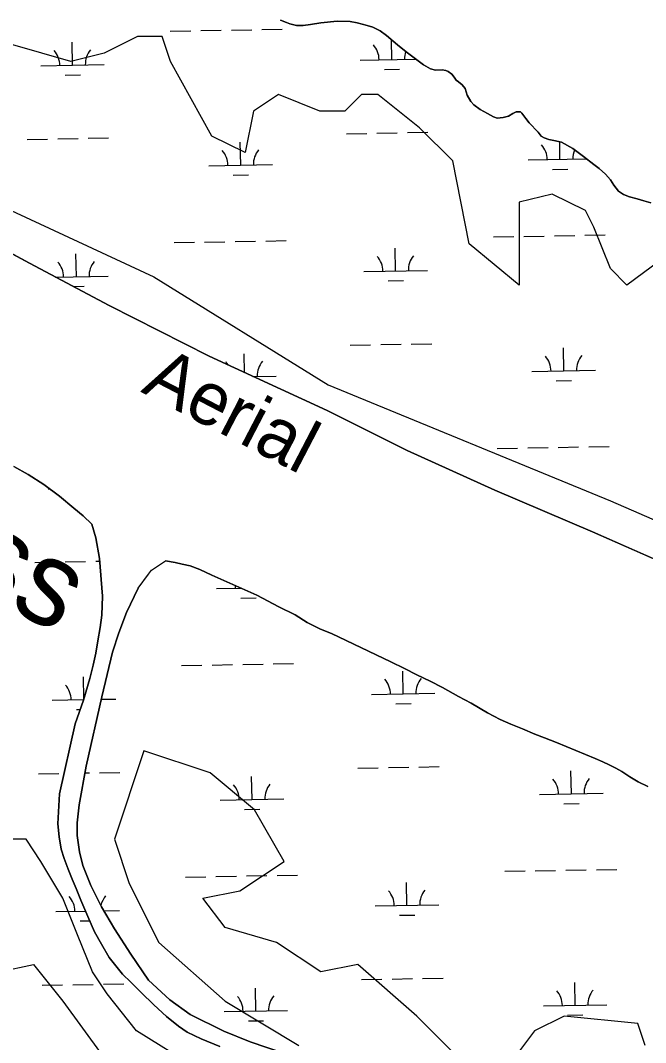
# Model space of a CAD drawing. Extents: x 3914892 to 3953151, y 242587 to 268572.
# Drawn here: x 3945998 to 3946980, y 254674 to 256282 of the extents above; entities that cross this region are included whole.
import ezdxf

# ---------------------------------------------------------------- set-up
doc = ezdxf.new("R2010")
doc.units = 0
for name, color, linetype in [('V-RIVR-IDEN', 7, 'Continuous'), ('V-SITE-VEGE', 7, 'Continuous'), ('V-TOPO-SHOR', 7, 'Continuous'), ('V-WETL-SWMP', 7, 'Continuous')]:
    doc.layers.add(name, color=color, linetype=linetype)

msp = doc.modelspace()

# ---------------------------------------------------------------- linework, layer by layer
at = {"layer": 'V-SITE-VEGE'}
for points in [[(3947003.4, 255904.8), (3946951.2, 255865.7), (3946925.1, 255891.8), (3946899, 255957), (3946886, 255983.1), (3946833.8, 256009.1), (3946781.6, 255996.1), (3946781.6, 255917.8), (3946781.6, 255865.7), (3946703.4, 255930.9), (3946677.3, 256061.3), (3946625.1, 256113.5), (3946559.9, 256165.7), (3946533.8, 256165.7), (3946507.7, 256139.6), (3946468.6, 256139.6), (3946403.4, 256165.7), (3946364.3, 256139.6), (3946351.2, 256074.4), (3946299, 256100.4), (3946233.8, 256217.8), (3946220.8, 256257), (3946181.7, 256257), (3946129.5, 256230.9), (3946077.3, 256217.8), (3945986, 256243.9)], [(3945646.9, 256139.6), (3946207.7, 255878.7), (3946481.6, 255709.1), (3946925.1, 255526.5), (3947225.1, 255396.1)], [(3946678.6, 254658.3), (3946620.7, 254716.2), (3946528, 254797.3), (3946470.1, 254785.8), (3946400.6, 254832.1), (3946319.5, 254855.3), (3946284.7, 254901.6), (3946342.7, 254913.2), (3946412.2, 254959.5), (3946365.8, 255040.6), (3946296.3, 255098.6), (3946192.1, 255133.3), (3946145.7, 254994.3), (3946168.9, 254924.8), (3946215.2, 254832.1), (3946319.5, 254739.4), (3946435.4, 254669.9)], [(3946273.2, 254635.1), (3946180.5, 254693.1), (3946134.1, 254751), (3946111, 254785.8), (3946087.8, 254843.7), (3946064.6, 254901.6), (3946029.9, 254959.5), (3946006.7, 254994.3), (3945960.4, 254994.3)], [(3945856.1, 254762.6), (3946018.3, 254797.3), (3946064.6, 254739.4), (3946157.3, 254612)], [(3946979.9, 254669.9), (3946968.3, 254704.7), (3946852.4, 254716.2), (3946806.1, 254693.1), (3946771.3, 254646.7)]]:
    msp.add_lwpolyline(points, dxfattribs=at)
at = {"layer": 'V-TOPO-SHOR'}
for points in [[(3946792.3, 256128.1), (3946786.1, 256136.6), (3946783.7, 256138.2), (3946781.1, 256138.3), (3946777.1, 256138.5), (3946772.1, 256136), (3946764.9, 256131.7), (3946756.5, 256129.3), (3946747.1, 256128.6), (3946741.3, 256130.7), (3946732.1, 256135.6), (3946720.4, 256142.2), (3946710.6, 256149.5), (3946705.8, 256154.7), (3946700.2, 256164.8), (3946696.8, 256175), (3946692.3, 256180.8), (3946686.4, 256185.7), (3946682.6, 256188.5), (3946679.5, 256193.2), (3946676, 256197.8), (3946670.3, 256202.1), (3946666.5, 256203.7), (3946660.6, 256204.4), (3946650.2, 256204), (3946642.5, 256205.9), (3946631.4, 256212.4), (3946618.8, 256221.8), (3946604.2, 256232.7), (3946590.4, 256243.9), (3946573.3, 256258.7), (3946563.1, 256266), (3946552, 256271.6), (3946542.9, 256274.5), (3946527, 256278.5), (3946516.3, 256280.3), (3946496, 256281.2), (3946470, 256278.6), (3946453.7, 256275.6), (3946442.5, 256274), (3946431.9, 256274.4), (3946421.6, 256276.7), (3946415.9, 256279), (3946406.9, 256282.7)], [(3946988.7, 255995.3), (3946977.8, 255998.7), (3946967.3, 256001.4), (3946955, 256004.6), (3946945.7, 256008.5), (3946938, 256013.8), (3946930.8, 256023.1), (3946925.1, 256031.7), (3946917.3, 256040.4), (3946907.3, 256049.3), (3946899.4, 256055.8), (3946882.7, 256068.4), (3946866.1, 256080.8), (3946848.1, 256090.7), (3946836.4, 256093.2), (3946828.3, 256094.9), (3946820.9, 256097.4), (3946816.6, 256100.1), (3946811.5, 256106.3), (3946797.6, 256120.9), (3946792.3, 256128.1)], [(3945916.1, 255951.8), (3946012, 255900.5), (3946137.4, 255833.6), (3946294.5, 255753.9), (3946480.1, 255668.6), (3946605.9, 255605.7), (3946743.7, 255543.1), (3946897.2, 255477.8), (3947054, 255408.5)], [(3946110.1, 255490.1), (3946096.6, 255502.9), (3946081.7, 255515), (3946059.2, 255534.1), (3946034.9, 255552.2), (3946009.9, 255567.8), (3945987.5, 255580.4)], [(3946127, 255376.4), (3946122, 255436.1), (3946116.7, 255468.6), (3946110.1, 255490.1)], [(3946183.1, 255389.4), (3946199, 255411.2), (3946203.7, 255417.5), (3946225.9, 255432.3)], [(3946369.7, 255378.4), (3946298.8, 255409.7), (3946279.8, 255418.4), (3946264.7, 255424.3), (3946252.3, 255426.9), (3946241, 255429.4), (3946225.9, 255432.3)], [(3946183.1, 255389.4), (3946164.8, 255351.1), (3946152.4, 255319.2), (3946142.9, 255288.4), (3946125.9, 255218.2), (3946101, 255109.4), (3946090.5, 255048.4), (3946086.9, 255019.9), (3946087.2, 255000.1), (3946090.7, 254974.5), (3946096, 254953), (3946108.8, 254921.3), (3946125.3, 254888.2), (3946145.6, 254853.1), (3946171.2, 254813.3), (3946199.4, 254772.7), (3946232.7, 254741.7), (3946264.9, 254718.6), (3946317.7, 254692.4), (3946358.9, 254675.8), (3946413.2, 254657.3)], [(3946311.4, 254668.3), (3946282, 254680.5), (3946260.2, 254690.8), (3946246.2, 254700.5), (3946227.3, 254715.6), (3946207.8, 254733.7), (3946187.8, 254753.1), (3946171.5, 254769.2), (3946158.6, 254782.3), (3946137.4, 254808.3), (3946125.1, 254829.4), (3946114.6, 254848.7), (3946103.7, 254873), (3946092.8, 254898.3), (3946085.5, 254916.6), (3946079.3, 254931.6), (3946072.9, 254947.3), (3946066.8, 254964), (3946061.9, 254978.6), (3946058.7, 254997.8), (3946056.7, 255018.7), (3946059.6, 255065.5), (3946083.9, 255176), (3946097, 255213), (3946107.1, 255246.9), (3946112.2, 255267.9), (3946116.7, 255287), (3946119.5, 255306.1), (3946123.1, 255327.1), (3946125.9, 255346.8), (3946127, 255376.4)], [(3946983.8, 255077.3), (3946969, 255084.5), (3946955.7, 255092.2), (3946943.1, 255100.9), (3946933.7, 255106), (3946923.5, 255111.5), (3946913.2, 255116.2), (3946901.4, 255121.4), (3946840.6, 255146.3), (3946821.5, 255153.8), (3946806.2, 255159.6), (3946787.2, 255167.7), (3946768.5, 255175.4), (3946752.1, 255182.4), (3946732, 255193.2), (3946706.2, 255208.5), (3946686.5, 255218.9), (3946661.3, 255233.1), (3946642, 255243.1), (3946620.9, 255253), (3946601.6, 255262.9), (3946580, 255273.2), (3946486.8, 255318), (3946469.7, 255324.8), (3946448.6, 255335.2), (3946429.8, 255347.3), (3946404.2, 255359.7), (3946369.7, 255378.4)]]:
    msp.add_lwpolyline(points, dxfattribs=at)
at = {"layer": 'V-WETL-SWMP'}
for p, q in [((3946406.9, 256282.7), (3946415.9, 256279)), ((3946415.9, 256279), (3946421.6, 256276.7)), ((3946421.6, 256276.7), (3946431.9, 256274.4)), ((3946431.9, 256274.4), (3946442.5, 256274)), ((3946442.5, 256274), (3946453.7, 256275.6)), ((3946453.7, 256275.6), (3946470, 256278.6)), ((3946470, 256278.6), (3946496, 256281.2)), ((3946496, 256281.2), (3946516.3, 256280.3)), ((3946516.3, 256280.3), (3946527, 256278.5)), ((3946527, 256278.5), (3946542.9, 256274.5)), ((3946542.9, 256274.5), (3946552, 256271.6)), ((3946233.5, 256265.3), (3946265.5, 256265.9)), ((3946281.5, 256266.2), (3946313.5, 256266.7)), ((3946329.5, 256267), (3946361.5, 256267.6)), ((3946377.5, 256267.9), (3946409.5, 256268.4)), ((3946552, 256271.6), (3946563.1, 256266)), ((3946563.1, 256266), (3946573.3, 256258.7)), ((3946573.3, 256258.7), (3946590.4, 256243.9)), ((3946079.8, 256211.8), (3946079.2, 256247.8)), ((3946581.7, 256220.8), (3946581.1, 256251.9)), ((3946590.4, 256243.9), (3946604.2, 256232.7)), ((3946604.2, 256232.7), (3946618.8, 256221.8)), ((3946029.8, 256210.9), (3946129.8, 256212.7)), ((3946531.7, 256219.9), (3946619.3, 256221.4)), ((3946618.8, 256221.8), (3946631.4, 256212.4)), ((3946631.4, 256212.4), (3946642.5, 256205.9)), ((3946068.1, 256196.2), (3946092.1, 256196.6)), ((3946569.9, 256205.1), (3946593.9, 256205.6)), ((3946642.5, 256205.9), (3946650.2, 256204)), ((3946650.2, 256204), (3946660.6, 256204.4)), ((3946660.6, 256204.4), (3946666.5, 256203.7)), ((3946666.5, 256203.7), (3946670.3, 256202.1)), ((3946670.3, 256202.1), (3946676, 256197.8)), ((3946676, 256197.8), (3946679.5, 256193.2)), ((3946679.5, 256193.2), (3946682.6, 256188.5)), ((3946682.6, 256188.5), (3946686.4, 256185.7)), ((3946686.4, 256185.7), (3946692.3, 256180.8)), ((3946692.3, 256180.8), (3946696.8, 256175)), ((3946696.8, 256175), (3946700.2, 256164.8)), ((3946700.2, 256164.8), (3946705.8, 256154.7)), ((3946705.8, 256154.7), (3946710.6, 256149.5)), ((3946710.6, 256149.5), (3946720.4, 256142.2)), ((3946720.4, 256142.2), (3946732.1, 256135.6)), ((3946732.1, 256135.6), (3946741.3, 256130.7)), ((3946741.3, 256130.7), (3946747.1, 256128.6)), ((3946747.1, 256128.6), (3946756.5, 256129.3)), ((3946756.5, 256129.3), (3946764.9, 256131.7)), ((3946764.9, 256131.7), (3946772.1, 256136)), ((3946772.1, 256136), (3946777.1, 256138.5)), ((3946777.1, 256138.5), (3946781.1, 256138.3)), ((3946781.1, 256138.3), (3946783.7, 256138.2)), ((3946783.7, 256138.2), (3946786.1, 256136.6)), ((3946786.1, 256136.6), (3946792.3, 256128.1)), ((3946792.3, 256128.1), (3946797.6, 256120.9)), ((3946797.6, 256120.9), (3946811.5, 256106.3)), ((3946008.5, 256095.1), (3946040.5, 256095.6)), ((3946056.5, 256095.9), (3946088.5, 256096.5)), ((3946104.5, 256096.8), (3946136.5, 256097.4)), ((3946510.3, 256104), (3946542.3, 256104.6)), ((3946558.3, 256104.9), (3946590.3, 256105.5)), ((3946606.3, 256105.8), (3946638.3, 256106.3)), ((3946811.5, 256106.3), (3946816.6, 256100.1)), ((3946816.6, 256100.1), (3946820.9, 256097.4)), ((3946820.9, 256097.4), (3946828.3, 256094.9)), ((3946344.1, 256054.6), (3946343.5, 256090.6)), ((3946828.3, 256094.9), (3946836.4, 256093.2)), ((3946836.4, 256093.2), (3946848.1, 256090.7)), ((3946845.9, 256063.6), (3946845.5, 256091.3)), ((3946848.1, 256090.7), (3946866.1, 256080.8)), ((3946866.1, 256080.8), (3946882.7, 256068.4)), ((3946796, 256062.7), (3946888, 256064.4)), ((3946882.7, 256068.4), (3946899.4, 256055.8)), ((3946294.1, 256053.7), (3946394.1, 256055.5)), ((3946834.2, 256048), (3946858.2, 256048.4)), ((3946899.4, 256055.8), (3946907.3, 256049.3)), ((3946907.3, 256049.3), (3946917.3, 256040.4)), ((3946332.4, 256039), (3946356.4, 256039.4)), ((3946917.3, 256040.4), (3946925.1, 256031.7)), ((3946925.1, 256031.7), (3946930.8, 256023.1)), ((3946930.8, 256023.1), (3946938, 256013.8)), ((3946938, 256013.8), (3946945.7, 256008.5)), ((3946945.7, 256008.5), (3946955, 256004.6)), ((3946955, 256004.6), (3946967.3, 256001.4)), ((3946967.3, 256001.4), (3946977.8, 255998.7)), ((3946977.8, 255998.7), (3946988.7, 255995.3)), ((3946012, 255900.5), (3945916.1, 255951.8)), ((3946335.4, 255934.4), (3946367.4, 255935)), ((3946383.4, 255935.2), (3946415.4, 255935.8)), ((3946741.3, 255941.7), (3946773.3, 255942.2)), ((3946789.3, 255942.5), (3946821.3, 255943.1)), ((3946837.3, 255943.4), (3946869.2, 255943.9)), ((3946885.2, 255944.2), (3946917.2, 255944.8)), ((3946239.4, 255932.7), (3946271.4, 255933.2)), ((3946287.4, 255933.5), (3946319.4, 255934.1)), ((3946587.6, 255888.2), (3946587, 255924.1)), ((3946085.8, 255879.2), (3946085.1, 255915.2)), ((3946137.4, 255833.6), (3946012, 255900.5)), ((3946537.6, 255887.3), (3946637.6, 255889)), ((3946053.1, 255878.6), (3946135.8, 255880.1)), ((3946575.9, 255872.5), (3946599.9, 255872.9)), ((3946081, 255863.7), (3946098.1, 255864)), ((3946294.5, 255753.9), (3946137.4, 255833.6)), ((3946350, 255728.4), (3946349.4, 255758)), ((3946516.3, 255771.4), (3946548.3, 255772)), ((3946564.3, 255772.3), (3946596.3, 255772.9)), ((3946612.3, 255773.1), (3946644.3, 255773.7)), ((3946851.9, 255731), (3946851.3, 255767)), ((3946480.1, 255668.6), (3946294.5, 255753.9)), ((3946801.9, 255730.1), (3946901.9, 255731.9)), ((3946363.3, 255722.3), (3946400.1, 255722.9)), ((3946840.2, 255715.3), (3946864.2, 255715.8)), ((3946605.9, 255605.7), (3946480.1, 255668.6)), ((3946743.7, 255543.1), (3946605.9, 255605.7)), ((3946747.2, 255609), (3946779.2, 255609.6)), ((3946795.2, 255609.9), (3946827.2, 255610.5)), ((3946843.2, 255610.7), (3946875.2, 255611.3)), ((3946891.2, 255611.6), (3946923.2, 255612.2)), ((3945987.5, 255580.4), (3946009.9, 255567.8)), ((3946009.9, 255567.8), (3946034.9, 255552.2)), ((3946034.9, 255552.2), (3946059.2, 255534.1)), ((3946041.7, 255545.7), (3946043.6, 255545.7)), ((3946059.2, 255534.1), (3946081.7, 255515)), ((3946897.2, 255477.8), (3946743.7, 255543.1)), ((3946081.7, 255515), (3946096.6, 255502.9)), ((3946096.6, 255502.9), (3946110.1, 255490.1)), ((3946110.1, 255490.1), (3946116.7, 255468.6)), ((3946116.7, 255468.6), (3946122, 255436.1)), ((3947054, 255408.5), (3946897.2, 255477.8)), ((3946020.4, 255429.8), (3946052.4, 255430.4)), ((3946068.4, 255430.7), (3946100.4, 255431.3)), ((3946116.4, 255431.5), (3946122.4, 255431.6)), ((3946122, 255436.1), (3946127, 255376.4)), ((3946203.7, 255417.5), (3946225.9, 255432.3)), ((3946225.9, 255432.3), (3946241, 255429.4)), ((3946241, 255429.4), (3946252.3, 255426.9)), ((3946252.3, 255426.9), (3946264.7, 255424.3)), ((3946264.7, 255424.3), (3946279.8, 255418.4)), ((3946183.1, 255389.4), (3946199, 255411.2)), ((3946199, 255411.2), (3946203.7, 255417.5)), ((3946279.8, 255418.4), (3946298.8, 255409.7)), ((3946298.8, 255409.7), (3946369.7, 255378.4)), ((3946164.8, 255351.1), (3946183.1, 255389.4)), ((3946306, 255388.5), (3946345.3, 255389.2)), ((3946127, 255376.4), (3946125.9, 255346.8)), ((3946344.3, 255373.7), (3946368.3, 255374.2)), ((3946369.7, 255378.4), (3946404.2, 255359.7)), ((3946404.2, 255359.7), (3946429.8, 255347.3)), ((3946125.9, 255346.8), (3946123.1, 255327.1)), ((3946152.4, 255319.2), (3946164.8, 255351.1)), ((3946429.8, 255347.3), (3946448.6, 255335.2)), ((3946123.1, 255327.1), (3946119.5, 255306.1)), ((3946448.6, 255335.2), (3946469.7, 255324.8)), ((3946469.7, 255324.8), (3946486.8, 255318)), ((3946142.9, 255288.4), (3946152.4, 255319.2)), ((3946486.8, 255318), (3946580, 255273.2)), ((3946119.5, 255306.1), (3946116.7, 255287)), ((3946116.7, 255287), (3946112.2, 255267.9)), ((3946125.9, 255218.2), (3946142.9, 255288.4)), ((3946112.2, 255267.9), (3946107.1, 255246.9)), ((3946251.3, 255267.4), (3946283.3, 255268)), ((3946299.3, 255268.3), (3946331.3, 255268.9)), ((3946347.3, 255269.1), (3946379.3, 255269.7)), ((3946395.3, 255270), (3946427.3, 255270.6)), ((3946580, 255273.2), (3946601.6, 255262.9)), ((3946601.6, 255262.9), (3946620.9, 255253)), ((3946097.7, 255215.2), (3946097, 255249.9)), ((3946107.1, 255246.9), (3946097, 255213)), ((3946599.5, 255222.9), (3946598.9, 255258.9)), ((3946620.9, 255253), (3946642, 255243.1)), ((3946642, 255243.1), (3946661.3, 255233.1)), ((3946661.3, 255233.1), (3946686.5, 255218.9)), ((3946047.7, 255213), (3946097.3, 255213.9)), ((3946097, 255213), (3946083.9, 255176)), ((3946101, 255109.4), (3946125.9, 255218.2)), ((3946125, 255214.4), (3946147.7, 255214.8)), ((3946549.5, 255222), (3946649.5, 255223.8)), ((3946686.5, 255218.9), (3946706.2, 255208.5)), ((3946086, 255198.3), (3946091.8, 255198.4)), ((3946587.8, 255207.3), (3946611.8, 255207.7)), ((3946706.2, 255208.5), (3946732, 255193.2)), ((3946732, 255193.2), (3946752.1, 255182.4)), ((3946752.1, 255182.4), (3946768.5, 255175.4)), ((3946083.9, 255176), (3946059.6, 255065.5)), ((3946768.5, 255175.4), (3946787.2, 255167.7)), ((3946787.2, 255167.7), (3946806.2, 255159.6)), ((3946806.2, 255159.6), (3946821.5, 255153.8)), ((3946821.5, 255153.8), (3946840.6, 255146.3)), ((3946840.6, 255146.3), (3946901.4, 255121.4)), ((3946901.4, 255121.4), (3946913.2, 255116.2)), ((3946913.2, 255116.2), (3946923.5, 255111.5)), ((3946090.5, 255048.4), (3946101, 255109.4)), ((3946122.3, 255098.9), (3946154.3, 255099.5)), ((3946528.2, 255106.2), (3946560.2, 255106.8)), ((3946576.2, 255107), (3946608.2, 255107.6)), ((3946624.2, 255107.9), (3946656.2, 255108.5)), ((3946863.8, 255065.7), (3946863.2, 255101.7)), ((3946923.5, 255111.5), (3946933.7, 255106)), ((3946933.7, 255106), (3946943.1, 255100.9)), ((3946943.1, 255100.9), (3946955.7, 255092.2)), ((3946026.4, 255097.2), (3946058.3, 255097.8)), ((3946099.1, 255098.5), (3946106.3, 255098.6)), ((3946362, 255056.8), (3946361.3, 255092.8)), ((3946955.7, 255092.2), (3946969, 255084.5)), ((3946969, 255084.5), (3946983.8, 255077.3)), ((3946813.8, 255064.9), (3946913.8, 255066.6)), ((3946059.6, 255065.5), (3946056.7, 255018.7)), ((3946312, 255055.9), (3946412, 255057.7)), ((3946852.1, 255050.1), (3946876.1, 255050.5)), ((3946086.9, 255019.9), (3946090.5, 255048.4)), ((3946350.3, 255041.1), (3946374.2, 255041.6)), ((3946056.7, 255018.7), (3946058.7, 254997.8)), ((3946087.2, 255000.1), (3946086.9, 255019.9)), ((3946058.7, 254997.8), (3946061.9, 254978.6)), ((3946090.7, 254974.5), (3946087.2, 255000.1)), ((3946061.9, 254978.6), (3946066.8, 254964)), ((3946096, 254953), (3946090.7, 254974.5)), ((3946066.8, 254964), (3946072.9, 254947.3)), ((3946072.9, 254947.3), (3946079.3, 254931.6)), ((3946108.8, 254921.3), (3946096, 254953)), ((3946401.3, 254937.4), (3946433.3, 254938)), ((3946759.1, 254943.8), (3946791.1, 254944.4)), ((3946807.1, 254944.6), (3946839.1, 254945.2)), ((3946855.1, 254945.5), (3946887.1, 254946.1)), ((3946903.1, 254946.4), (3946935.1, 254946.9)), ((3946079.3, 254931.6), (3946085.5, 254916.6)), ((3946257.3, 254934.8), (3946289.3, 254935.4)), ((3946305.3, 254935.7), (3946337.3, 254936.2)), ((3946353.3, 254936.5), (3946385.3, 254937.1)), ((3946605.5, 254890.3), (3946604.8, 254926.3)), ((3946085.5, 254916.6), (3946092.8, 254898.3)), ((3946125.3, 254888.2), (3946108.8, 254921.3)), ((3946092.8, 254898.3), (3946103.7, 254873)), ((3946555.5, 254889.4), (3946655.5, 254891.2)), ((3946053.6, 254880.4), (3946100.1, 254881.2)), ((3946145.6, 254853.1), (3946125.3, 254888.2)), ((3946129.1, 254881.8), (3946153.6, 254882.2)), ((3946593.7, 254874.6), (3946617.7, 254875.1)), ((3946091.9, 254865.7), (3946106.8, 254865.9)), ((3946103.7, 254873), (3946114.6, 254848.7)), ((3946114.6, 254848.7), (3946125.1, 254829.4)), ((3946171.2, 254813.3), (3946145.6, 254853.1)), ((3946125.1, 254829.4), (3946137.4, 254808.3)), ((3946199.4, 254772.7), (3946171.2, 254813.3)), ((3946137.4, 254808.3), (3946158.6, 254782.3)), ((3946158.6, 254782.3), (3946171.5, 254769.2)), ((3946032.3, 254764.6), (3946064.3, 254765.2)), ((3946080.3, 254765.4), (3946112.3, 254766)), ((3946128.3, 254766.3), (3946160.3, 254766.9)), ((3946171.5, 254769.2), (3946187.8, 254753.1)), ((3946232.7, 254741.7), (3946199.4, 254772.7)), ((3946534.1, 254773.6), (3946566.1, 254774.1)), ((3946582.1, 254774.4), (3946614.1, 254775)), ((3946630.1, 254775.3), (3946662.1, 254775.8)), ((3946869.8, 254733.1), (3946869.1, 254769.1)), ((3946187.8, 254753.1), (3946207.8, 254733.7)), ((3946367.9, 254724.1), (3946367.3, 254760.1)), ((3946207.8, 254733.7), (3946227.3, 254715.6)), ((3946264.9, 254718.6), (3946232.7, 254741.7)), ((3946819.8, 254732.2), (3946919.7, 254734)), ((3946227.3, 254715.6), (3946246.3, 254700.5)), ((3946317.7, 254692.4), (3946264.9, 254718.6)), ((3946317.9, 254723.3), (3946417.9, 254725)), ((3946858, 254717.5), (3946882, 254717.9)), ((3946246.3, 254700.5), (3946260.2, 254690.8)), ((3946356.2, 254708.5), (3946380.2, 254708.9)), ((3946260.2, 254690.8), (3946282, 254680.5)), ((3946358.9, 254675.8), (3946317.7, 254692.4)), ((3946282, 254680.5), (3946311.4, 254668.3)), ((3946413.2, 254657.3), (3946358.9, 254675.8))]:
    msp.add_line(p, q, dxfattribs=at)
for centre, start, end in [((3946526.4, 256220.3), 0.2532, 41.7968), ((3946024.6, 256211.3), 0.2532, 41.7968), ((3946135.1, 256213.3), 140.2532, 181.7968), ((3946636.9, 256222.2), 161.7341, 181.7968), ((3946790.7, 256063.1), 0.2532, 41.7968), ((3946288.9, 256054.1), 0.2532, 41.7968), ((3946399.3, 256056.1), 140.2532, 181.7968), ((3946901.2, 256065.1), 157.0571, 181.7968), ((3946141, 255880.6), 140.2532, 181.7968), ((3946532.4, 255887.6), 0.2532, 41.7968), ((3946642.8, 255889.6), 140.2532, 181.7968), ((3946030.5, 255878.7), 0.2532, 41.7968), ((3946294.8, 255721.5), 31.551, 41.7968), ((3946405.3, 255723.5), 140.2532, 181.7968), ((3946796.7, 255730.5), 0.2532, 41.7968), ((3946907.1, 255732.5), 140.2532, 181.7968), ((3946300.8, 255388.9), 0.2532, 7.4438), ((3946544.3, 255222.4), 0.2532, 41.7968), ((3946654.7, 255224.4), 140.2532, 181.7968), ((3946042.4, 255213.4), 0.2532, 41.7968), ((3946808.6, 255065.2), 0.2532, 41.7968), ((3946919, 255067.2), 140.2532, 181.7968), ((3946306.7, 255056.3), 0.2532, 41.7968), ((3946417.2, 255058.2), 140.2532, 181.7968), ((3946550.2, 254889.8), 0.2532, 41.7968), ((3946660.7, 254891.7), 140.2532, 181.7968), ((3946048.4, 254880.8), 0.2532, 41.7968), ((3946158.9, 254882.8), 140.2532, 167.9854), ((3946312.7, 254723.6), 0.2532, 41.7968), ((3946423.1, 254725.6), 140.2532, 181.7968), ((3946814.5, 254732.6), 0.2532, 41.7968), ((3946925, 254734.6), 140.2532, 181.7968)]:
    msp.add_arc(centre, 35.2, start, end, dxfattribs=at)

# ---------------------------------------------------------------- texts
at = {"layer": 'V-RIVR-IDEN'}
for s, height, rotation, p in [('Aerial', 83, 332.5407, (3946185.8, 255698.5)), ('Pass', 133, 331.0515, (3945709.5, 255508))]:
    msp.add_text(s, height=height, rotation=rotation, dxfattribs=at).set_placement(p)

doc.saveas('drawing.dxf')
